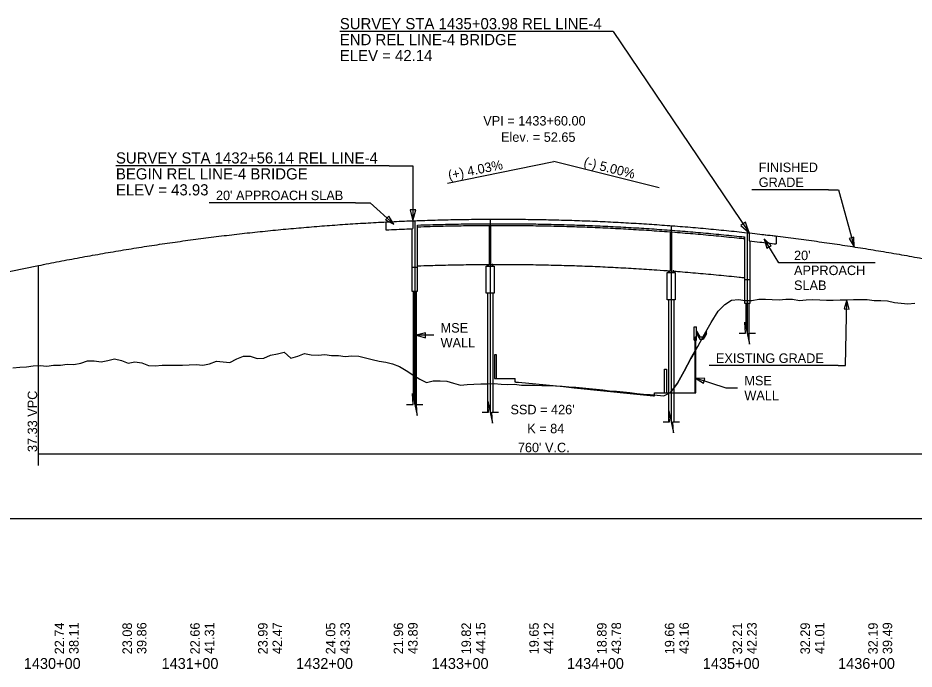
# Model space of a CAD drawing. Extents: x 2360994 to 2383826, y 330623 to 403123.
# Drawn here: x 2371290 to 2371951, y 366762 to 367242 of the extents above; entities that cross this region are included whole.
import ezdxf

# ---------------------------------------------------------------- set-up
doc = ezdxf.new("R2010")
doc.units = 0
for name, color, linetype in [('BR_CENTER LINES', 7, 'Continuous'), ('BR_CONCRETE', 7, 'Continuous'), ('BR_DETAILS', 7, 'Continuous'), ('BR_STRUCTURAL STEEL', 7, 'Continuous'), ('RD_DDB_GradeTX', 7, 'Continuous'), ('RD_DDB_Profile_EX', 7, 'Continuous'), ('RD_DDB_Profile_Lbl', 7, 'Continuous'), ('RD_DDB_Profile_PR', 7, 'Continuous'), ('RD_DDB_StaTX', 7, 'Continuous'), ('RD_DDB_StripGrade', 7, 'Continuous'), ('RD_DDB_VCLbl', 7, 'Continuous'), ('RD_GPK_Profile_Cell', 7, 'Continuous'), ('RD_PD_MedBWall', 7, 'Continuous'), ('RD_TX_Profile', 7, 'Continuous')]:
    doc.layers.add(name, color=color, linetype=linetype)

msp = doc.modelspace()

# ---------------------------------------------------------------- linework, layer by layer
at = {"layer": 'BR_CENTER LINES'}
for p, q in [((2371583, 367092.6), (2371583, 366957.04)), ((2371638.71, 367093.73), (2371638.71, 366951.39)), ((2371772.21, 367088.92), (2371772.21, 366944.16)), ((2371828.25, 367083.74), (2371828.25, 367009.66))]:
    msp.add_line(p, q, dxfattribs=at)
at = {"layer": 'BR_CONCRETE'}
for p, q in [((2371561.71, 367091.68), (2371561.71, 367085.85)), ((2371581.71, 367092.56), (2371581.71, 367086.72)), ((2371580.91, 367086.69), (2371580.91, 367058.05)), ((2371585.09, 367058.05), (2371585.09, 367089.35)), ((2371638.21, 367060.35), (2371638.21, 367089.14)), ((2371639.21, 367060.35), (2371639.21, 367089.14)), ((2371771.71, 367055.58), (2371771.71, 367084.37)), ((2371772.71, 367055.5), (2371772.71, 367084.3)), ((2371829.54, 367083.6), (2371829.54, 367077.77)), ((2371826.16, 367080.64), (2371826.16, 367049.34)), ((2371830.34, 367049.34), (2371830.34, 367077.68)), ((2371849.54, 367081.29), (2371849.54, 367075.45)), ((2371585.09, 367058.05), (2371580.91, 367058.05)), ((2371826.16, 367049.34), (2371830.34, 367049.34)), ((2371636.71, 367039.1), (2371636.71, 366951.39)), ((2371640.71, 367039.1), (2371640.71, 366951.39)), ((2371770.21, 367034.29), (2371770.21, 366944.16)), ((2371774.21, 367034.29), (2371774.21, 366944.16))]:
    msp.add_line(p, q, dxfattribs=at)
for points in [[(2371580.91, 367058.05), (2371580.91, 367040.55), (2371585.09, 367040.55), (2371585.09, 367058.05)], [(2371826.16, 367049.34), (2371826.16, 367031.84), (2371830.34, 367031.84), (2371830.34, 367049.34)]]:
    msp.add_lwpolyline(points, dxfattribs=at)
for points in [[(2371635.72, 367059.1), (2371641.7, 367059.1), (2371641.7, 367039.1), (2371635.72, 367039.1)], [(2371637.21, 367059.1), (2371636.71, 367059.1), (2371636.71, 367060.36), (2371637.21, 367060.36)], [(2371640.21, 367059.1), (2371640.71, 367059.1), (2371640.71, 367060.36), (2371640.21, 367060.36)], [(2371769.22, 367054.29), (2371775.2, 367054.29), (2371775.2, 367034.29), (2371769.22, 367034.29)], [(2371770.71, 367054.29), (2371770.21, 367054.29), (2371770.21, 367055.55), (2371770.71, 367055.55)], [(2371773.71, 367054.29), (2371774.21, 367054.29), (2371774.21, 367055.55), (2371773.71, 367055.55)]]:
    msp.add_lwpolyline(points, close=True, dxfattribs=at)
for points in [[(2371561.71, 367091.68), (2371563.97, 367091.79), (2371579.17, 367092.46), (2371594.37, 367092.98), (2371609.57, 367093.37), (2371624.77, 367093.62), (2371639.97, 367093.73), (2371655.17, 367093.71), (2371670.37, 367093.54), (2371685.57, 367093.24), (2371700.77, 367092.81), (2371715.97, 367092.23), (2371731.17, 367091.52), (2371746.37, 367090.67), (2371761.57, 367089.69), (2371776.77, 367088.57), (2371791.97, 367087.31), (2371807.17, 367085.91), (2371822.37, 367084.37), (2371837.57, 367082.7), (2371849.54, 367081.29)], [(2371585.09, 367089.35), (2371594.37, 367089.65), (2371609.57, 367090.03), (2371624.77, 367090.28), (2371639.97, 367090.4), (2371655.17, 367090.37), (2371670.37, 367090.21), (2371685.57, 367089.91), (2371700.77, 367089.47), (2371715.97, 367088.9), (2371731.17, 367088.19), (2371746.37, 367087.34), (2371761.57, 367086.36), (2371776.77, 367085.23), (2371791.97, 367083.97), (2371807.17, 367082.57), (2371822.37, 367081.04), (2371826.16, 367080.64)], [(2371561.71, 367085.85), (2371563.97, 367085.96), (2371579.17, 367086.62), (2371581.71, 367086.72)], [(2371585.09, 367088.1), (2371594.37, 367088.4), (2371609.57, 367088.78), (2371624.77, 367089.03), (2371639.97, 367089.15), (2371655.17, 367089.12), (2371670.37, 367088.96), (2371685.57, 367088.66), (2371700.77, 367088.22), (2371715.97, 367087.65), (2371731.17, 367086.94), (2371746.37, 367086.09), (2371761.57, 367085.11), (2371776.77, 367083.98), (2371791.97, 367082.72), (2371807.17, 367081.32), (2371822.37, 367079.79), (2371826.16, 367079.39)], [(2371829.54, 367077.77), (2371837.57, 367076.87), (2371849.54, 367075.45)], [(2371585.09, 367059.3), (2371594.37, 367059.61), (2371609.57, 367059.99), (2371624.77, 367060.24), (2371638.21, 367060.35)], [(2371639.21, 367060.35), (2371639.97, 367060.35), (2371655.17, 367060.33), (2371670.37, 367060.17), (2371685.57, 367059.87), (2371700.77, 367059.43), (2371715.97, 367058.86), (2371731.17, 367058.15), (2371746.37, 367057.3), (2371761.57, 367056.31), (2371771.71, 367055.58)], [(2371772.71, 367055.5), (2371776.77, 367055.19), (2371791.97, 367053.93), (2371807.17, 367052.53), (2371822.37, 367051), (2371826.16, 367050.59)]]:
    msp.add_spline(points, degree=3, dxfattribs=at)
at = {"layer": 'BR_DETAILS'}
for p, q in [((2371827, 367009.66), (2371826.51, 367017.74)), ((2371826.51, 367017.74), (2371829.97, 367001.65)), ((2371822.24, 367009.66), (2371827, 367009.66)), ((2371829.97, 367001.65), (2371829.48, 367009.66)), ((2371829.48, 367009.66), (2371834.24, 367009.66)), ((2371789.72, 366965.68), (2371789.72, 366996.33)), ((2371581.76, 366957.04), (2371581.27, 366965.12)), ((2371581.27, 366965.12), (2371584.72, 366949.03)), ((2371771.3, 366965.68), (2371775.41, 366965.68)), ((2371775.41, 366965.68), (2371787.34, 366965.68)), ((2371787.34, 366965.68), (2371789.72, 366965.68)), ((2371637.47, 366951.39), (2371636.97, 366959.47)), ((2371636.97, 366959.47), (2371640.43, 366943.38)), ((2371577, 366957.04), (2371581.76, 366957.04)), ((2371584.72, 366949.03), (2371584.24, 366957.04)), ((2371584.24, 366957.04), (2371589, 366957.04)), ((2371632.7, 366951.39), (2371637.47, 366951.39)), ((2371640.43, 366943.38), (2371639.94, 366951.39)), ((2371639.94, 366951.39), (2371644.7, 366951.39)), ((2371770.97, 366944.16), (2371770.47, 366952.24)), ((2371770.47, 366952.24), (2371773.93, 366936.15)), ((2371766.2, 366944.16), (2371770.97, 366944.16)), ((2371773.93, 366936.15), (2371773.44, 366944.16)), ((2371773.44, 366944.16), (2371778.2, 366944.16))]:
    msp.add_line(p, q, dxfattribs=at)
msp.add_lwpolyline([(2371789.72, 366996.33), (2371786.72, 366990.92), (2371781.72, 366981.71), (2371776.72, 366972.79), (2371771.72, 366965.88), (2371771.3, 366965.68)], dxfattribs=at)
at = {"layer": 'BR_STRUCTURAL STEEL'}
for p, q in [((2371581.91, 367040.55), (2371581.91, 366962.12)), ((2371582.97, 367040.55), (2371582.97, 366957.22)), ((2371583.04, 367040.55), (2371583.04, 366956.86)), ((2371584.09, 367040.55), (2371584.09, 366951.96)), ((2371827.16, 367031.84), (2371827.16, 367014.74)), ((2371828.21, 367031.84), (2371828.21, 367009.83)), ((2371828.29, 367031.84), (2371828.29, 367009.48)), ((2371829.34, 367031.84), (2371829.34, 367004.58))]:
    msp.add_line(p, q, dxfattribs=at)
at = {"layer": 'RD_DDB_GradeTX'}
for p in [(2371607.14, 367120.34), (2371763.18, 367116.74)]:
    msp.add_line(p, (2371685.57, 367136.14), dxfattribs=at)
at = {"layer": 'RD_DDB_Profile_EX'}
for points in [[(2371476.72, 366993.32), (2371481.72, 366994.33), (2371486.72, 366995.57), (2371491.72, 366991.2), (2371496.72, 366992.59), (2371501.72, 366994.6), (2371506.72, 366993.78), (2371511.72, 366993.46), (2371516.72, 366993.96), (2371521.72, 366993.29), (2371526.72, 366993.09), (2371531.72, 366992.49), (2371536.72, 366993), (2371541.72, 366992.78), (2371546.72, 366991.39), (2371551.72, 366990.3), (2371556.72, 366989.03), (2371561.72, 366988.17), (2371566.72, 366987.04), (2371571.72, 366985.08), (2371576.72, 366981.99), (2371581.72, 366978.85), (2371586.72, 366975.81), (2371591.72, 366973.33), (2371596.72, 366974.51), (2371601.72, 366974.54), (2371606.72, 366974.24), (2371611.72, 366972.81), (2371616.72, 366971.41), (2371621.72, 366971.77), (2371626.72, 366972.05), (2371631.72, 366972.16), (2371636.72, 366972.27), (2371641.72, 366972.63), (2371646.72, 366972.08), (2371651.72, 366971.77), (2371656.72, 366971.98), (2371661.72, 366971.38), (2371666.72, 366971.29), (2371671.72, 366971.19), (2371676.72, 366971.09), (2371681.72, 366970.95), (2371686.72, 366970.79), (2371691.72, 366970.6), (2371696.72, 366970.18), (2371701.72, 366969.77), (2371706.72, 366969.35), (2371711.72, 366968.82), (2371716.72, 366968.28), (2371721.72, 366967.73), (2371726.72, 366967.19), (2371731.72, 366966.91), (2371736.72, 366966.34), (2371741.72, 366965.76), (2371746.72, 366965.21), (2371751.72, 366964.76), (2371756.72, 366964.31), (2371761.72, 366963.89), (2371766.72, 366963.49), (2371771.72, 366965.88), (2371776.72, 366972.79), (2371781.72, 366981.71), (2371786.72, 366990.92), (2371791.72, 366999.91), (2371796.72, 367008.79), (2371801.72, 367017.58), (2371806.72, 367025.75), (2371811.72, 367030.88), (2371816.72, 367033.95), (2371821.72, 367034.47), (2371826.72, 367033.78), (2371831.72, 367033.76), (2371836.72, 367034.72), (2371841.72, 367034.72), (2371846.72, 367034.38), (2371851.72, 367034.23), (2371856.72, 367034.61), (2371861.72, 367034.7), (2371866.72, 367033.8), (2371871.72, 367034.26), (2371876.72, 367034.37), (2371881.72, 367034.21), (2371886.72, 367034.02), (2371891.72, 367033.92), (2371896.72, 367034.21), (2371901.72, 367034.23), (2371906.72, 367034.55), (2371911.72, 367034.53), (2371916.72, 367034.41), (2371921.72, 367033.82), (2371926.72, 367033.82), (2371931.72, 367033.37), (2371936.72, 367032.21), (2371941.72, 367031.72), (2371946.72, 367031.26), (2371951.72, 367031.76)], [(2371286.72, 366984), (2371291.72, 366984.54), (2371296.72, 366984.82), (2371301.72, 366985.5), (2371306.72, 366985.71), (2371311.72, 366985.38), (2371316.72, 366986.02), (2371321.72, 366986.04), (2371326.72, 366986.73), (2371331.72, 366986.58), (2371336.72, 366987.49), (2371341.72, 366989.25), (2371346.72, 366989.22), (2371351.72, 366988.61), (2371356.72, 366989.56), (2371361.72, 366990.76), (2371366.72, 366989.51), (2371371.72, 366987.43), (2371376.72, 366988.51), (2371381.72, 366987.85), (2371386.72, 366985.75), (2371391.72, 366985.64), (2371396.72, 366986.07), (2371401.72, 366986.05), (2371406.72, 366986.01), (2371411.72, 366986.06), (2371416.72, 366986.36), (2371421.72, 366986.52), (2371426.72, 366986.08), (2371431.72, 366986.91), (2371436.72, 366988.87), (2371441.72, 366988.61), (2371446.72, 366988.12), (2371451.72, 366990.75), (2371456.72, 366992.73), (2371461.72, 366992.79), (2371466.72, 366991.08), (2371471.72, 366991.09), (2371476.72, 366993.32)]]:
    msp.add_lwpolyline(points, dxfattribs=at)
at = {"layer": 'RD_DDB_Profile_PR'}
for p, q in [((2371215.47, 367041.38), (2371305.57, 367059.54)), ((2371641.77, 366976.09), (2371657.06, 366976.09)), ((2371657.06, 366973.56), (2371657.06, 366976.09)), ((2371657.61, 366973.56), (2371657.06, 366973.56)), ((2371657.61, 366973.56), (2371659.52, 366973.38)), ((2371659.52, 366973.38), (2371692.83, 366970.23)), ((2371692.83, 366970.23), (2371700.59, 366969.43)), ((2371700.59, 366969.43), (2371744.38, 366964.98)), ((2371744.38, 366964.98), (2371759.2, 366963.38)), ((2371759.75, 366965.68), (2371775.41, 366965.68)), ((2371759.75, 366963.31), (2371759.75, 366965.68)), ((2371775.41, 366965.68), (2371787.34, 366965.68)), ((2371787.34, 366965.68), (2371790.32, 366965.68)), ((2371759.2, 366963.38), (2371759.75, 366963.31))]:
    msp.add_line(p, q, dxfattribs=at)
msp.add_spline([(2371305.57, 367059.54), (2371320.77, 367062.54), (2371335.97, 367065.4), (2371351.17, 367068.12), (2371366.37, 367070.7), (2371381.57, 367073.15), (2371396.77, 367075.46), (2371411.97, 367077.63), (2371427.17, 367079.66), (2371442.37, 367081.56), (2371457.57, 367083.32), (2371472.77, 367084.94), (2371487.97, 367086.43), (2371503.17, 367087.78), (2371518.37, 367088.99), (2371533.57, 367090.06), (2371548.77, 367091), (2371563.97, 367091.79), (2371579.17, 367092.46), (2371594.37, 367092.98), (2371609.57, 367093.37), (2371624.77, 367093.62), (2371639.97, 367093.73), (2371655.17, 367093.71), (2371670.37, 367093.54), (2371685.57, 367093.24), (2371700.77, 367092.81), (2371715.97, 367092.23), (2371731.17, 367091.52), (2371746.37, 367090.67), (2371761.57, 367089.69), (2371776.77, 367088.57), (2371791.97, 367087.31), (2371807.17, 367085.91), (2371822.37, 367084.37), (2371837.57, 367082.7), (2371852.77, 367080.89), (2371867.97, 367078.94), (2371883.17, 367076.86), (2371898.37, 367074.64), (2371913.57, 367072.28), (2371928.77, 367069.78), (2371943.97, 367067.15), (2371959.17, 367064.38), (2371974.37, 367061.47), (2371989.57, 367058.43), (2372004.77, 367055.25), (2372019.97, 367051.93), (2372035.17, 367048.47), (2372050.37, 367044.88), (2372065.57, 367041.14)], degree=3, dxfattribs=at)
at = {"layer": 'RD_DDB_VCLbl'}
for p, q in [((2371305.57, 366912.13), (2371305.57, 367059.54)), ((2371305.57, 366920.55), (2372065.57, 366920.55))]:
    msp.add_line(p, q, dxfattribs=at)
at = {"layer": 'RD_GPK_Profile_Cell'}
msp.add_line((2368825.57, 366872.88), (2372725.57, 366872.88), dxfattribs=at)
at = {"layer": 'RD_PD_MedBWall'}
for p, q in [((2371789.13, 367004.4), (2371789.13, 367014.4)), ((2371789.13, 367014.4), (2371790.92, 367014.4)), ((2371790.92, 367004.4), (2371790.92, 367014.4)), ((2371790.92, 367011.06), (2371793.3, 367006.94)), ((2371798.07, 367011.06), (2371795.69, 367006.94)), ((2371798.07, 367009.4), (2371798.07, 367011.06)), ((2371789.13, 367004.4), (2371789.72, 367004.4)), ((2371789.72, 366965.68), (2371789.72, 367006.9)), ((2371789.72, 367006.9), (2371790.32, 367006.9)), ((2371790.32, 366965.68), (2371790.32, 367006.9)), ((2371790.32, 367004.4), (2371790.92, 367004.4)), ((2371790.92, 367009.4), (2371793.3, 367005.27)), ((2371793.3, 367006.94), (2371795.69, 367006.94)), ((2371793.3, 367005.27), (2371795.69, 367005.27)), ((2371798.07, 367009.4), (2371795.69, 367005.27))]:
    msp.add_line(p, q, dxfattribs=at)
for points in [[(2371643.26, 366976.09), (2371643.26, 366993.59), (2371641.77, 366993.59), (2371641.77, 366976.09)], [(2371767.13, 366965.68), (2371767.13, 366983.18), (2371768.62, 366983.18), (2371768.62, 366965.68)]]:
    msp.add_lwpolyline(points, dxfattribs=at)
at = {"layer": 'RD_TX_Profile'}
for p, q in [((2371729.37, 367232.04), (2371527.78, 367232.04)), ((2371564.26, 367133.01), (2371362.67, 367133.01)), ((2371888.14, 367115.44), (2371831.71, 367115.44)), ((2371539.3, 367105.77), (2371431.44, 367105.77)), ((2371922.61, 367061.49), (2371857.74, 367061.49)), ((2371895.25, 366985.7), (2371800.12, 366985.7))]:
    msp.add_line(p, q, dxfattribs=at)
for points in [[(2371729.37, 367232.04), (2371729.37, 367232.04), (2371829.54, 367083.6)], [(2371564.26, 367133.01), (2371581.71, 367133.01), (2371581.71, 367092.56)], [(2371888.14, 367115.44), (2371895.65, 367115.44), (2371906.97, 367073.35)], [(2371539.3, 367105.77), (2371550.17, 367105.77), (2371567.62, 367089.98)], [(2371857.74, 367061.49), (2371851.49, 367061.49), (2371840.75, 367079.17)], [(2371895.25, 366985.7), (2371900.75, 366985.7), (2371901.72, 367034.23)], [(2371597.1, 367008.09), (2371588.59, 367008.09), (2371584.11, 367008.09)], [(2371821.12, 366969.15), (2371812.58, 366969.15), (2371790.03, 366976.51)]]:
    msp.add_lwpolyline(points, dxfattribs=at)
for points in [[(2371579.58, 367100.51), (2371581.71, 367092.56), (2371583.84, 367100.51)], [(2371561.39, 367093.17), (2371567.62, 367089.98), (2371563.82, 367095.86)], [(2371823.46, 367089.15), (2371829.54, 367083.6), (2371827.05, 367091.45)], [(2371845.81, 367074.33), (2371840.75, 367079.17), (2371842.71, 367072.45)], [(2371903.46, 367079.41), (2371906.97, 367073.35), (2371906.96, 367080.35)], [(2371903.39, 367027.43), (2371901.72, 367034.23), (2371899.77, 367027.5)], [(2371590.88, 367009.9), (2371584.11, 367008.09), (2371590.88, 367006.27)], [(2371797.02, 366976.13), (2371790.03, 366976.51), (2371795.89, 366972.69)]]:
    msp.add_lwpolyline(points, close=True, dxfattribs=at)

# ---------------------------------------------------------------- texts
at = {"layer": 'RD_DDB_GradeTX'}
for s, rotation, p in [('(+) 4.03%', 11.39718, (2371608.41, 367122.63)), ('(-) 5.00%', 345.96376, (2371707.15, 367132.81))]:
    msp.add_text(s, height=7, rotation=rotation, dxfattribs=at).set_placement(p)
at = {"layer": 'RD_DDB_Profile_Lbl'}
for s, p in [('VPI = 1433+60.00', (2371633.59, 367162.79)), ('Elev. = 52.65', (2371646.68, 367150.77))]:
    msp.add_text(s, height=7, dxfattribs=at).set_placement(p)
at = {"layer": 'RD_DDB_StaTX'}
for s, p in [('1430+00', (2371294.71, 366762)), ('1431+00', (2371396.32, 366762)), ('1432+00', (2371495.52, 366762)), ('1433+00', (2371595.55, 366762)), ('1434+00', (2371695.31, 366762)), ('1435+00', (2371795.44, 366762)), ('1436+00', (2371895.22, 366762))]:
    msp.add_text(s, height=8, dxfattribs=at).set_placement(p)
at = {"layer": 'RD_DDB_StripGrade'}
for s, p in [('37.33 VPC', (2371304.57, 366921.96)), ('22.74', (2371324.48, 366772.77)), ('38.11', (2371335.15, 366772.95)), ('23.08', (2371374.48, 366772.77)), ('39.86', (2371385.15, 366772.95)), ('22.66', (2371424.48, 366772.77)), ('41.31', (2371435.15, 366772.95)), ('23.99', (2371474.48, 366772.77)), ('42.47', (2371485.15, 366772.95)), ('24.05', (2371524.48, 366772.77)), ('43.33', (2371535.15, 366772.95)), ('21.96', (2371574.48, 366772.77)), ('43.89', (2371585.15, 366772.95)), ('19.82', (2371624.48, 366772.77)), ('44.15', (2371635.15, 366772.95)), ('19.65', (2371674.48, 366772.77)), ('44.12', (2371685.15, 366772.95)), ('18.89', (2371724.48, 366772.77)), ('43.78', (2371735.15, 366772.95)), ('19.66', (2371774.48, 366772.77)), ('43.16', (2371785.15, 366772.95)), ('32.21', (2371824.48, 366772.77)), ('42.23', (2371835.15, 366772.95)), ('32.29', (2371874.48, 366772.77)), ('41.01', (2371885.15, 366772.95)), ('32.19', (2371924.48, 366772.77)), ('39.49', (2371935.15, 366772.95))]:
    msp.add_text(s, height=7, rotation=90, dxfattribs=at).set_placement(p)
at = {"layer": 'RD_DDB_VCLbl'}
for s, p in [("SSD = 426'", (2371653.62, 366949.8)), ('K = 84', (2371666, 366935.8)), ("760' V.C.", (2371659.07, 366921.8))]:
    msp.add_text(s, height=7, dxfattribs=at).set_placement(p)
at = {"layer": 'RD_TX_Profile'}
for s, height, p in [('SURVEY STA 1435+03.98 REL LINE-4', 8.2353, (2371527.78, 367233.8)), ('END REL LINE-4 BRIDGE', 8.2353, (2371527.78, 367222.04)), ('ELEV = 42.14', 8.2353, (2371527.78, 367210.27)), ('SURVEY STA 1432+56.14 REL LINE-4', 8.2353, (2371362.67, 367134.78)), ('BEGIN REL LINE-4 BRIDGE', 8.2353, (2371362.67, 367123.01)), ('FINISHED', 7, (2371836.71, 367128.44)), ('GRADE', 7, (2371836.71, 367117.44)), ('ELEV = 43.93', 8.2353, (2371362.67, 367111.25)), ("20' APPROACH SLAB", 7, (2371436.44, 367107.77)), ("20'", 7, (2371862.74, 367063.49)), ('APPROACH', 7, (2371862.74, 367052.49)), ('SLAB', 7, (2371862.74, 367041.49)), ('MSE', 7, (2371602.1, 367010.09)), ('WALL', 7, (2371602.1, 366999.09)), ('EXISTING GRADE', 7, (2371805.12, 366987.7)), ('MSE', 7, (2371826.12, 366971.15)), ('WALL', 7, (2371826.12, 366960.15))]:
    msp.add_text(s, height=height, dxfattribs=at).set_placement(p)

doc.saveas('drawing.dxf')
